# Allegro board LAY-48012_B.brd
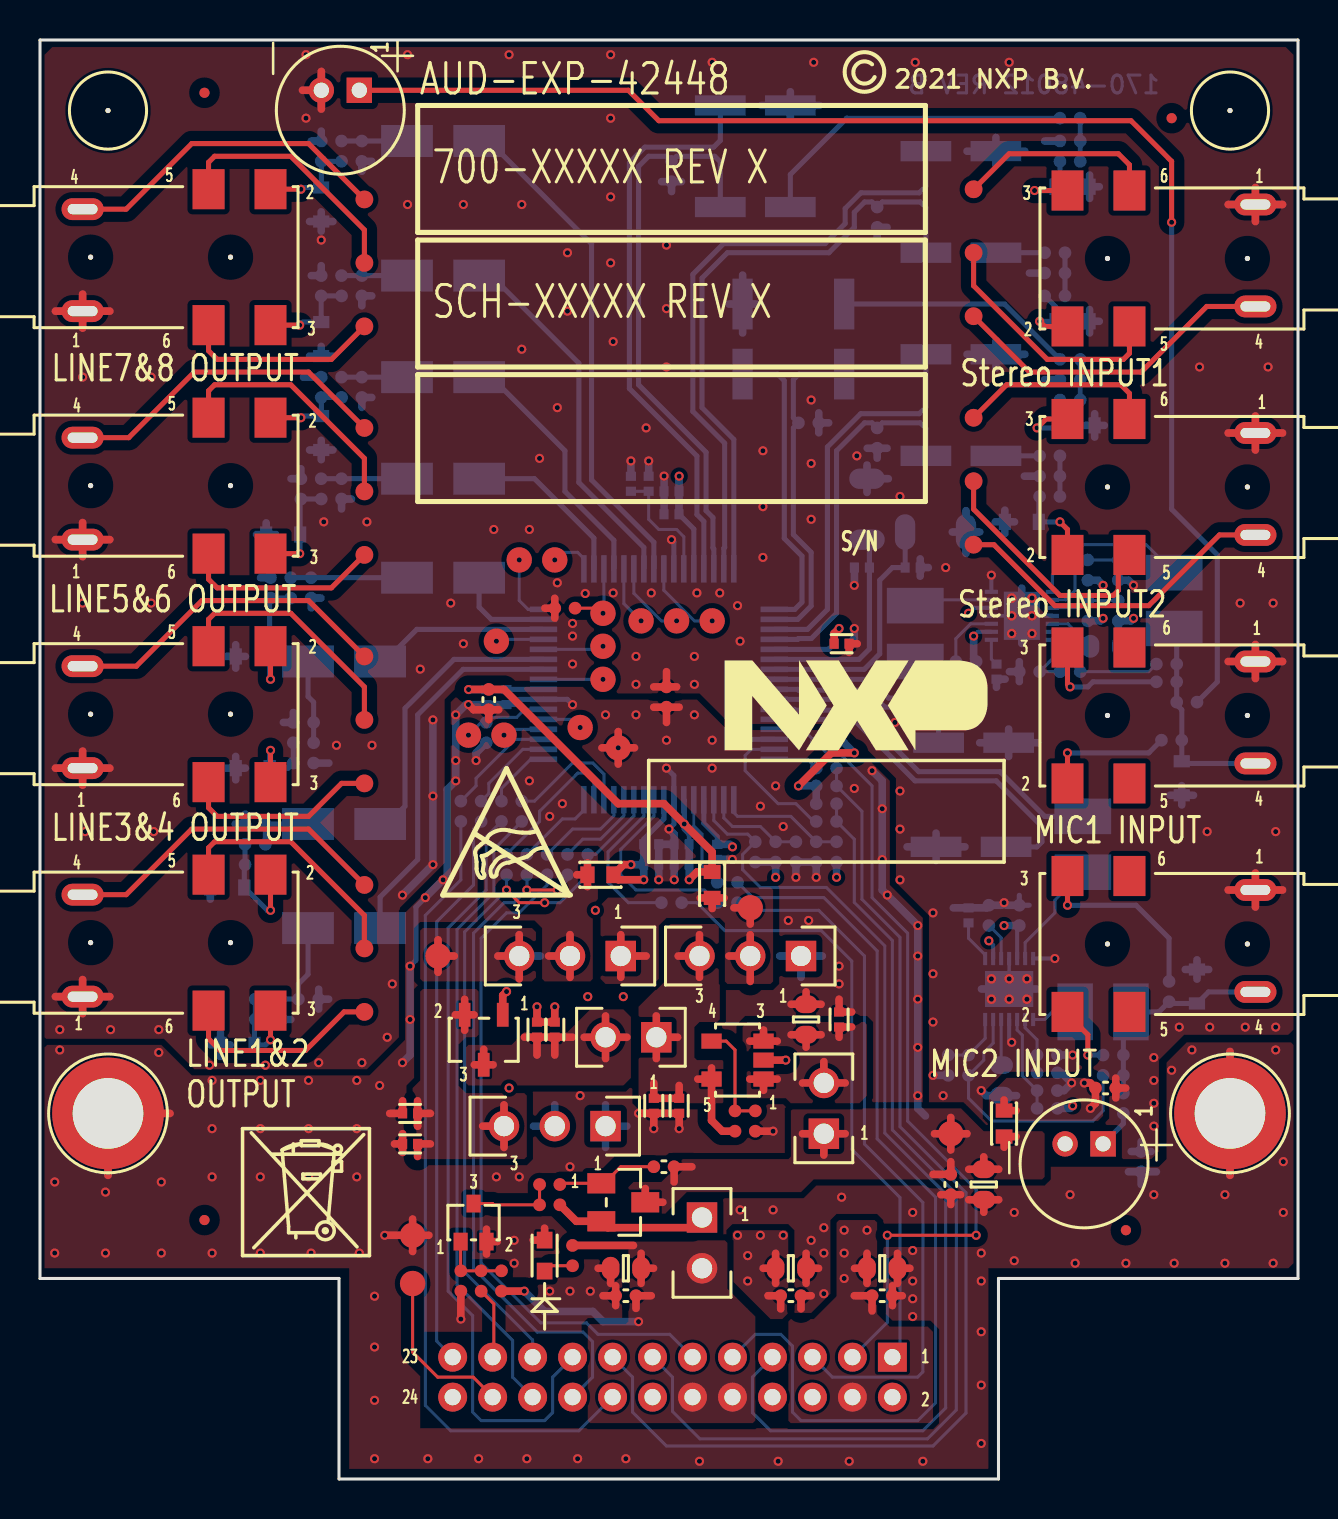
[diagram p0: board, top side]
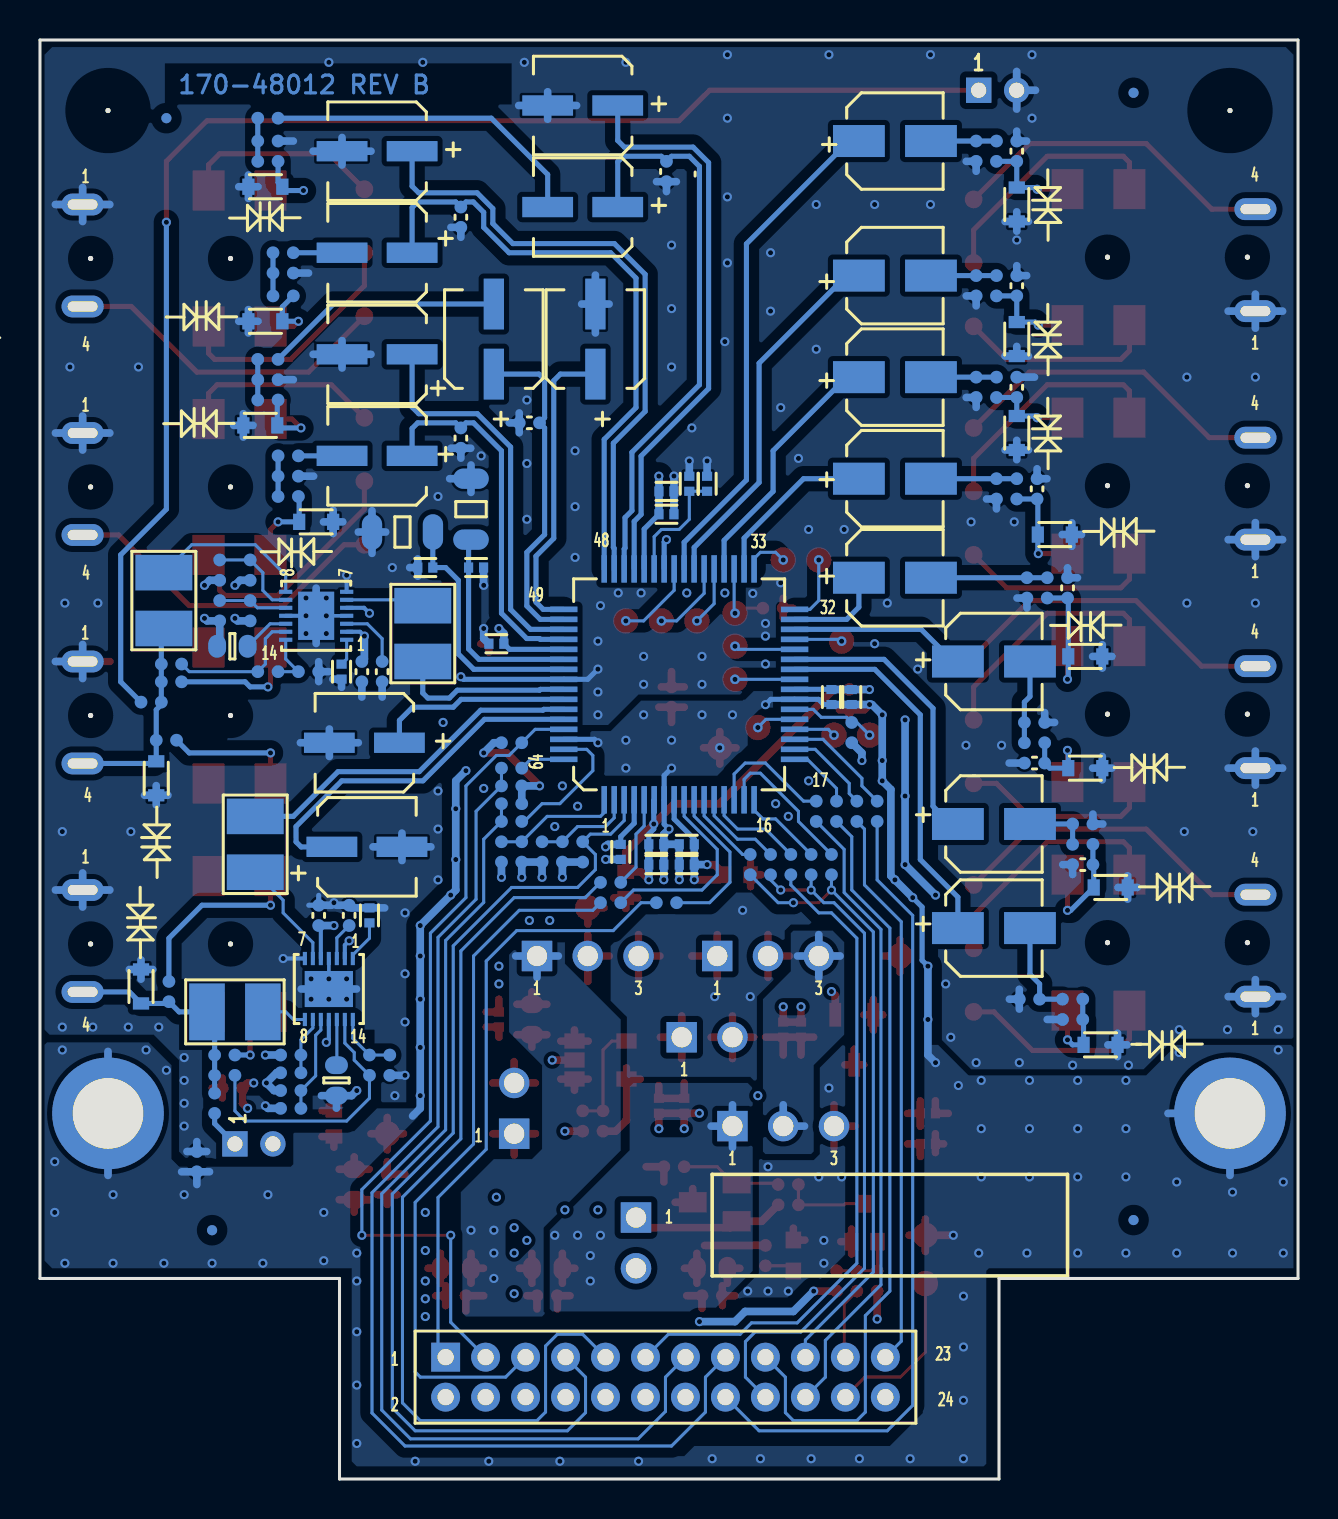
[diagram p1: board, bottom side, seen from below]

Outline 62.94 x 71.98 mm; copper layers: TOP, L2_GND1, L3_GND2, BOTTOM. Coordinates in mm from the lower left corner of the outline.
Outline path: 0,71.98 0,10.03 14.96,10.03 14.96,0 47.96,0 47.96,10.03 62.94,10.03 62.94,71.98 0,71.98

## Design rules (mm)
constraint set DEFAULT: min track width 0.152
net group CODEC_AUX_IN1: nets CODEC_AUX_IN1_N CODEC_AUX_IN1_P
net group CODEC_AUX_IN2: nets CODEC_AUX_IN2_N CODEC_AUX_IN2_P
net group CODEC_AUX_IN3: nets CODEC_AUX_IN3_N CODEC_AUX_IN3_P
net group CODEC_AUX_IN4: nets CODEC_AUX_IN4_N CODEC_AUX_IN4_P
net group CODEC_MIC1: nets CODEC_MIC1_N CODEC_MIC1_P
net group CODEC_MIC2: nets CODEC_MIC2_N CODEC_MIC2_P
net group 3W: nets ADC_LRCK ADC_SCLK AUX_LRCK AUX_SCLK DAC_LRCK DAC_SCLK DC_I2S1_MCLK DC_I2S1_RX_BCLK DC_I2S1_TX_BCLK SCL_CCLK
nets with their own width: min track width 0.254; nets AIN_1 AIN_2 AOUT_1 AOUT_2 AOUT_3 AOUT_4 AOUT_5 AOUT_6 AOUT_7 AOUT_8 CODEC_AOUT1_P CODEC_AOUT2_P CODEC_AOUT3_P CODEC_AOUT4_P CODEC_AOUT5_P CODEC_AOUT6_P CODEC_AOUT7_P CODEC_AOUT8_P MICIN_1 MICIN_2
nets with their own width: min track width 0.381; nets AGND GND

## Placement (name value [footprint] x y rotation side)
C1  10uF  [CC0603_OV]  42.14 10.54 0 top
C2  0.1UF  [CC0402_25]  42.14 9.17 0 top
C3  10uF  [CC0603_OV]  37.57 10.54 0 top
C4  0.1UF  [CC0402_25]  37.57 9.17 0 top
C5  10uF  [CC0603_OV]  29.31 10.54 180 top
C6  0.1UF  [CC0402_25]  29.31 9.17 180 top
C7  10uF  [CC0603_OV]  47.22 14.73 270 top
C8  0.1UF  [CC0402_25]  45.57 14.73 270 top
C9  10uF  [CC0603_OV]  38.33 22.99 90 top
C10  0.1UF  [0402_CC]  39.98 22.99 90 top
C11  4.7uF  [0402_CC]  30.71 18.67 270 top
C12  0.1UF  [0402_CC]  31.98 18.67 270 top
C13  2200PF  [CC0402_25]  31.22 15.62 0 top
C14  4.7uF  [0402_CC]  24.87 22.48 90 top
C15  0.1UF  [0402_CC]  25.76 22.48 90 top
C16  4.7uF  [0402_CC]  18.52 16.76 180 top
C17  0.1UF  [0402_CC]  18.52 18.29 180 top
C18  10uF  [CC0402_25]  53.31 19.56 0 top
C19  0.1UF  [0402_CC]  40.11 41.78 0 bottom
C20  0.1UF  [0402_CC]  31.6 48.26 180 bottom
C21  0.01uF  [0402_CC]  40.11 41.78 0 top
C22  0.01uF  [0402_CC]  31.6 49.4 180 bottom
C23  0.1UF  [0402_CC]  29.57 49.78 90 bottom
C24  4.7uF  [0402_CC]  30.45 49.78 90 bottom
C25  0.1UF  [0402_CC]  43.66 45.59 0 bottom
C26  100uF  [CC1206_OV]  44.81 47.37 0 bottom
C27  10uF  [CC0402_25]  22.45 38.99 270 top
C28  0.1UF  [0402_CC]  22.33 39.12 270 bottom
C29  0.1UF  [0402_CC]  32.11 31.75 180 bottom
C30  0.01uF  [0402_CC]  23.34 39.12 270 bottom
C31  0.01uF  [0402_CC]  32.11 30.73 180 bottom
C32  0.1UF  [0402_CC]  41.12 45.59 180 bottom
C33  100uF  [CC1206_OV]  41.38 48.51 90 bottom
C34  4.7uF  [0402_CC]  30.58 30.73 0 bottom
C35  0.1UF  [0402_CC]  33.88 31.37 270 bottom
C36  0.01uF  [0402_CC]  30.58 31.75 0 bottom
C37  1uF  [CC0402_25]  46.84 40.39 270 bottom
C38  1uF  [CC0402_25]  49 28.19 90 bottom
C39  0.47uF  [CC0603_OV]  53.31 41.66 180 bottom
C40  0.47uF  [CC0603_OV]  48.11 19.94 90 bottom
C41  0.1uF  [CC1210]  56.74 43.94 90 bottom
C42  0.1uF  [CC1210]  43.79 42.29 270 bottom
C43  0.1uF  [CC1210]  53.19 23.37 180 bottom
C44  0.1uF  [CC1210]  52.17 31.75 90 bottom
C45  4.7uF  [CCE40X54]  46.58 31.62 180 bottom
C46  0.1UF  [0402_CC]  47.85 40.39 270 bottom
C47  2.2UF  [CC0402_25]  45.82 40.39 270 bottom
C48  0.1UF  [0402_CC]  46.46 28.19 90 bottom
C49  2.2UF  [CC0402_25]  47.47 28.19 90 bottom
C50  4.7uF  [CCE40X54]  46.71 36.83 0 bottom
C51  10UF  [CCE40X54]  35.79 63.63 0 bottom
C52  2200pF  [CC0402_25]  31.6 65.41 270 bottom
C53  4.7uF  [CCE40X54]  35.79 68.71 0 bottom
C54  10UF  [CCE40X54]  46.08 61.34 0 bottom
C55  2200pF  [CC0402_25]  41.88 63.12 270 bottom
C56  4.7uF  [CCE40X54]  46.08 66.42 0 bottom
C57  3.3uF  [CC_A5]  15.21 27.56 180 bottom
C58  3.3uF  [CC_A5]  20.17 50.04 180 bottom
C59  2200pF  [CC0402_25]  11.28 22.99 0 bottom
C60  2200pF  [CC0402_25]  13.06 49.53 90 bottom
C61  3.3uF  [CC_A5]  15.21 32.77 180 bottom
C62  3.3uF  [CC_A5]  20.17 55.12 180 bottom
C63  2200pF  [CC0402_25]  10.77 30.73 0 bottom
C64  2200pF  [CC0402_25]  14.07 54.61 90 bottom
C65  3.3uF  [CC_A5]  15.21 40.89 180 bottom
C66  3.3uF  [CC_A5]  20.17 60.2 180 bottom
C67  2200pF  [CC0402_25]  13.18 35.81 0 bottom
C68  2200pF  [CC0402_25]  14.07 59.69 90 bottom
C69  3.3uF  [CC_A5]  20.17 45.09 180 bottom
C70  3.3uF  [CC_A5]  20.17 66.93 180 bottom
C71  2200pF  [CC0402_25]  11.53 44.58 90 bottom
C72  2200pF  [CC0402_25]  14.07 66.42 90 bottom
C73  10UF  [CCE40X54]  40.23 57.02 90 bottom
C74  10UF  [CCE40X54]  46.08 51.18 0 bottom
C75  2200pF  [CC0402_25]  38.46 52.83 0 bottom
C76  2200pF  [CC0402_25]  41.88 52.07 270 bottom
C77  4.7uF  [CCE40X54]  35.15 57.02 90 bottom
C78  4.7uF  [CCE40X54]  46.08 56.26 0 bottom
D1  RED  [LED_0603]  25.25 11.18 90 top
FB1  120OHM  [0603_CC]  48.23 17.78 90 top
FB2  120OHM  [0603_CC]  33.63 29.72 90 top
FB3  120OHM  [0603_CC]  28.04 30.23 0 top
H1  .635" LONG  [SPACER_139T]  3.4 18.29 0 top
H2  .635" LONG  [SPACER_139T]  59.54 18.29 0 top
J1  CON 2X12  [CON24_2MM_TH]  42.65 6.1 180 bottom
J2  HDR 1X2  [HDR102]  33.12 13.08 0 top
J3  HDR_1X3  [HDR103]  38.07 26.16 270 top
J4  HDR_1X3  [HDR103]  28.3 17.65 270 top
J5  HDR_1X3  [HDR103]  29.06 26.16 270 top
J6  PJ31360-I  [CON6_AUDJACK_RA_TH]  2.13 24.13 0 top
J7  PJ31360-I  [CON6_AUDJACK_RA_TH]  2.13 35.56 0 top
J8  PJ31360-I  [CON6_AUDJACK_RA_TH]  2.13 46.99 0 top
J9  PJ31360-I  [CON6_AUDJACK_RA_TH]  2.13 58.42 0 top
J10  PJ31360-I  [CON6_AUDJACK_RA_TH]  60.81 40.89 180 top
J11  PJ31360-I  [CON6_AUDJACK_RA_TH]  60.81 29.46 180 top
J12  PJ31360-I  [CON6_AUDJACK_RA_TH]  60.81 63.75 180 top
J13  HDR 1X2  [HDR102]  39.22 17.27 180 top
J14  HDR 1X2  [HDR102]  30.84 22.1 270 top
J15  PJ31360-I  [CON6_AUDJACK_RA_TH]  60.81 52.32 180 top
NOREF  -  []  41.25 70.36 0 top
NOREF#2  -  []  -6.27 24.03 0 top
NOREF#3  -  []  54.51 23.36 0 top
NOREF#4  -  []  20.65 4.1 90 top
NOREF#5  -  []  50.21 57.7 90 top
NOREF#6  -  []  60.41 49.62 90 top
NOREF#7  -  []  2.53 49.69 0 top
NOREF#8  -  []  -6.27 46.89 0 top
NOREF#9  -  []  -6.27 46.89 0 top
NOREF#10  -  []  -6.27 24.03 0 top
NOREF#11  -  []  -24.32 -55.33 0 top
NOREF#12  -  []  2.53 26.83 0 top
NOREF#13  -  []  2.13 35.56 90 top
NOREF#14  -  []  60.41 61.05 0 top
NOREF#15  -  []  -6.27 24.03 0 top
NOREF#16  -  []  30.45 30.86 0 top
NOREF#17  -  []  51.41 23.36 0 top
NOREF#18  -  []  -6.27 35.46 0 top
NOREF#19  -  []  -6.27 58.32 0 top
NOREF#20  -  []  22.2 20.72 90 top
NOREF#21  -  []  60.41 49.62 0 top
NOREF#22  -  []  -6.27 46.89 90 top
NOREF#23  -  []  11.53 34.86 90 top
NOREF#24  -  []  53.41 49.62 0 top
NOREF#25  -  []  51.41 34.79 0 top
NOREF#26  -  []  54.51 46.22 0 top
NOREF#27  -  []  -6.27 59.74 0 top
NOREF#28  -  []  60.81 58.65 0 top
NOREF#29  -  []  2.53 61.12 90 top
NOREF#30  -  []  20.17 29.21 0 top
NOREF#31  -  []  -6.27 35.46 90 top
NOREF#32  -  []  2.13 24.13 90 top
NOREF#33  -  []  14.96 0 0 top
NOREF#34  -  []  51.41 57.65 90 top
NOREF#35  -  []  54.51 57.65 0 top
NOREF#36  -  []  60.41 38.19 0 top
NOREF#37  -  []  -6.27 71.17 0 top
NOREF#38  -  []  83.13 188.21 0 top
NOREF#39  -  []  51.41 46.22 90 top
NOREF#40  -  []  53.41 61.05 0 top
NOREF#41  -  []  51.41 23.36 90 top
NOREF#42  -  []  60.81 47.22 0 top
NOREF#43  -  []  2.53 38.26 0 top
NOREF#44  -  []  60.41 26.76 0 top
NOREF#45  -  []  10.13 11.18 0 top
NOREF#46  -  []  50.21 57.7 0 top
NOREF#47  -  []  -6.27 35.46 0 top
NOREF#48  -  []  21.25 23.22 0 top
NOREF#49  -  []  -6.27 35.46 0 top
NOREF#50  -  []  40.65 6.1 0 top
NOREF#51  -  [unnamed#2]  8.23 12.95 0 top
NOREF#52  -  []  63.06 34.84 0 top
NOREF#53  -  []  54.51 34.79 0 top
NOREF#54  -  []  60.41 61.05 90 top
NOREF#55  -  []  2.13 58.42 90 top
NOREF#56  -  []  -6.27 46.89 0 top
NOREF#57  -  []  -6.27 24.03 90 top
NOREF#58  -  []  -307.51 308.83 0 top
NOREF#59  -  []  60.81 58.65 90 top
NOREF#60  -  []  63.06 46.27 0 top
NOREF#61  -  []  60.81 35.79 90 top
NOREF#62  -  []  -6.27 46.89 0 top
NOREF#63  -  []  11.53 57.72 90 top
NOREF#64  -  []  20.65 4.1 0 top
NOREF#65  -  []  -6.27 35.46 0 top
NOREF#66  -  []  60.81 47.22 90 top
NOREF#67  -  []  -6.27 58.32 0 top
NOREF#68  -  []  0 10.03 90 top
NOREF#69  -  []  18.9 62.36 0 top
NOREF#70  -  []  18.9 55.63 0 top
NOREF#71  -  []  60.81 35.79 0 top
NOREF#72  -  []  -351.94 -178.82 0 top
NOREF#73  -  []  -6.27 46.89 0 top
NOREF#74  -  []  2.53 38.26 90 top
NOREF#75  -  [unnamed#2]  59.54 68.45 0 top
NOREF#76  -  [unnamed#2]  54.33 12.45 0 top
NOREF#77  -  []  0 71.98 0 top
NOREF#78  -  []  50.21 23.41 0 top
NOREF#79  -  []  51.41 57.65 0 top
NOREF#80  -  []  51.41 46.22 0 top
NOREF#81  -  []  -6.27 58.32 0 top
NOREF#82  -  []  50.21 34.84 0 top
NOREF#83  -  []  47.96 0 90 top
NOREF#84  -  []  50.21 46.27 0 top
NOREF#85  -  []  0 10.03 0 top
NOREF#86  -  []  60.81 24.36 0 top
NOREF#87  -  []  2.13 46.99 90 top
NOREF#88  -  []  11.53 23.43 90 top
NOREF#89  -  []  51.41 34.79 90 top
NOREF#90  -  []  60.41 26.76 90 top
NOREF#91  -  [unnamed#2]  56.62 68.07 270 top
NOREF#92  -  []  50.21 46.27 90 top
NOREF#93  -  []  2.53 26.83 90 top
NOREF#94  -  []  -6.27 58.32 0 top
NOREF#95  -  []  60.81 24.36 90 top
NOREF#96  -  []  -6.27 36.88 0 top
NOREF#97  -  []  68.7 2.97 90 top
NOREF#98  -  []  60.41 38.19 90 top
NOREF#99  -  []  44 2.97 0 top
NOREF#100  -  []  50.21 23.41 90 top
NOREF#101  -  []  34.26 36.45 0 top
NOREF#102  -  []  53.41 26.76 0 top
NOREF#103  -  []  -162.62 126.36 0 top
NOREF#104  -  []  20.65 22.87 0 top
NOREF#105  -  []  -6.27 58.32 0 top
NOREF#106  -  []  47.96 0 0 top
NOREF#107  -  []  -6.27 35.46 0 top
NOREF#108  -  []  63.06 23.41 0 top
NOREF#109  -  []  50.21 34.84 90 top
NOREF#110  -  []  -6.27 24.03 0 top
NOREF#111  -  []  2.53 61.12 0 top
NOREF#112  -  []  -6.27 58.32 90 top
NOREF#113  -  []  11.53 46.29 90 top
NOREF#114  -  []  -6.27 48.31 0 top
NOREF#115  -  []  2.53 49.69 90 top
NOREF#116  -  []  -6.27 24.03 0 top
NOREF#117  -  [unnamed#2]  3.4 68.45 0 top
NOREF#118  -  []  18.9 48.89 0 top
NOREF#119  -  []  53.41 38.19 0 top
NOREF#120  -  []  63.06 57.7 0 top
NOREF#121  -  []  20.65 21.07 90 top
NOREF#122  -  [unnamed#2]  8.23 69.34 90 top
NOREF#123  -  []  14.96 0 90 top
NOREF#124  -  []  29.31 10.16 180 bottom
NOREF#125  -  [unnamed#2]  54.33 12.45 180 bottom
NOREF#126  -  [unnamed#2]  56.62 68.07 90 bottom
NOREF#127  -  [unnamed#2]  8.23 69.34 270 bottom
NOREF#128  -  [unnamed#2]  8.23 12.95 180 bottom
P1  EM6022P  [MIC_WM-63PR]  15.98 69.47 90 top
P2  EM6022P  [MIC_WM-63PR]  53.19 16.76 90 top
Q1  IRLML6401  [SOT-23]  29.18 13.84 270 top
Q2  2N7002BKW  [SC70_3]  21.69 12.83 0 top
R1  470  [RC0402_25]  26.64 11.18 270 top
R2  47K  [RC0402_25]  25.5 13.72 180 top
R3  464K  [RC0402_25]  34.77 17.91 90 top
R4  0  [RC0402_25]  22.07 9.91 90 top
R5  100K  [RC0402_25]  25.5 14.73 0 top
R6  200K  [RC0402_25]  35.79 17.91 270 top
R7  100K  [RC0402_25]  21.06 9.91 270 top
R9  0  [RC0402_25]  31.6 28.83 180 bottom
R10  0  [RC0402_25]  34.39 28.83 180 bottom
R11  0  [RC0402_25]  34.39 29.84 180 bottom
R12  0  [RC0402_25]  25.37 30.73 90 bottom
R14  0  [RC0402_25]  26.39 30.73 90 bottom
R15  0  [RC0402_25]  22.07 33.4 90 bottom
R16  0  [RC0402_25]  21.06 33.4 90 bottom
R17  0  [RC0402_25]  23.09 33.4 90 bottom
R18  0  [RC0402_25]  24.36 30.73 90 bottom
R19  0  [RC0402_25]  23.34 30.73 90 bottom
R20  0  [RC0402_25]  24.1 33.4 90 bottom
R21  0  [RC0402_25]  39.34 32.89 180 bottom
R22  0  [RC0402_25]  39.34 35.56 180 bottom
R23  10.0K  [RC0402_25]  22.33 37.34 270 bottom
R24  10.0K  [RC0402_25]  39.34 36.83 0 bottom
R25  2.0K  [RC0402_25]  39.34 33.78 180 bottom
R26  10.0K  [RC0402_25]  35.79 31.37 270 bottom
R27  2.0K  [RC0402_25]  39.34 34.67 180 bottom
R28  0  [RC0402_25]  55.09 15.88 90 bottom
R29  10.0K  [RC0402_25]  39.85 31.37 270 bottom
R30  10.0K  [RC0402_25]  36.8 31.37 270 bottom
R31  10.0K  [RC0402_25]  38.84 31.37 270 bottom
R32  10.0K  [RC0402_25]  37.82 31.37 270 bottom
R33  10.0K  [RC0402_25]  26.26 43.56 180 top
R34  0  [RC0402_25]  50.39 20.32 0 bottom
R35  0  [RC0402_25]  52.43 45.47 270 bottom
R36  0  [RC0402_25]  53.95 45.47 270 bottom
R37  0  [RC0402_25]  50.39 21.21 0 bottom
R38  2.2K  [RC0402_25]  56.36 40.77 180 bottom
R39  2.2K  [RC0402_25]  53.7 20.19 180 bottom
R40  150K  [RC0402_25]  46.46 20.7 270 bottom
R41  100K  [RC0402_25]  45.44 20.7 270 bottom
R42  150K  [RC0402_25]  51.54 40.39 0 bottom
R43  100K  [RC0402_25]  49.5 40.39 180 bottom
R44  0  [RC0402_25]  50.39 19.43 0 bottom
R45  0  [RC0402_25]  50.39 18.54 0 bottom
R46  0  [RC0402_25]  52.43 43.43 270 bottom
R47  0  [RC0402_25]  53.95 43.43 270 bottom
R48  2.49K  [RC0402_25]  51.54 65.91 0 bottom
R49  0  [RC0402_25]  51.54 68.07 180 bottom
R50  2.49K  [RC0402_25]  51.54 66.93 0 bottom
R51  2.49K  [RC0402_25]  50.77 59.18 0 bottom
R52  0  [RC0402_25]  50.77 61.34 180 bottom
R53  2.49K  [RC0402_25]  50.77 60.33 0 bottom
R54  470  [RC0402_25]  11.28 24 180 bottom
R55  470  [RC0402_25]  14.07 49.53 270 bottom
R56  10.0K  [RC0402_25]  13.44 24 0 bottom
R57  10.0K  [RC0402_25]  15.09 49.53 270 bottom
R58  470  [RC0402_25]  10.77 31.75 180 bottom
R59  470  [RC0402_25]  15.09 54.61 270 bottom
R60  10.0K  [RC0402_25]  10.77 32.77 180 bottom
R61  10.0K  [RC0402_25]  16.1 54.61 270 bottom
R62  470  [RC0402_25]  13.18 36.83 180 bottom
R63  470  [RC0402_25]  15.09 59.69 270 bottom
R64  10.0K  [RC0402_25]  13.18 37.85 180 bottom
R65  10.0K  [RC0402_25]  16.1 59.69 270 bottom
R66  470  [RC0402_25]  12.55 44.58 270 bottom
R67  470  [RC0402_25]  15.09 66.42 270 bottom
R68  10.0K  [RC0402_25]  13.56 44.58 270 bottom
R69  10.0K  [RC0402_25]  16.1 66.42 270 bottom
R71  0  [RC0402_25]  56.36 39.88 180 bottom
R72  0  [RC0402_25]  56.62 36.96 180 bottom
R73  0  [RC0402_25]  53.7 21.21 180 bottom
R74  0  [RC0402_25]  56.49 24.38 90 bottom
R75  2.49K  [RC0402_25]  51.54 53.97 0 bottom
R76  2.49K  [RC0402_25]  51.54 54.99 0 bottom
R77  0  [RC0402_25]  51.54 56.01 180 bottom
R78  2.49K  [RC0402_25]  50.52 49.15 0 bottom
R79  2.49K  [RC0402_25]  50.52 50.16 0 bottom
R80  0  [RC0402_25]  50.52 51.18 180 bottom
R81  0  [RC0402_25]  27.41 30.73 90 bottom
R82  0  [RC0402_25]  31.34 39.12 90 top
R83  1.0K  [RC0402_25]  23.09 9.91 90 top
R84  0  [RC0402_25]  57.38 38.86 180 bottom
R85  0  [RC0402_25]  54.2 18.8 90 bottom
TP1  -  [TPAD_050]  18.64 9.78 0 top
TP2  -  [TPAD_050]  18.64 12.19 0 top
TP3  -  [TPAD_050]  28.93 36.58 270 top
TP4  -  [TPAD_050]  45.57 17.27 0 top
TP5  -  [TPAD_050]  35.53 28.58 270 top
TP6  -  [TPAD_050]  19.91 26.16 270 top
TP7  -  [TPAD_050]  22.83 41.91 0 top
TP8  -  [TPAD_050]  23.98 45.97 0 top
TP9  -  [TPAD_050]  28.17 40 0 top
TP10  -  [TPAD_050]  28.17 41.66 0 top
TP11  -  [TPAD_050]  25.76 45.97 0 top
TP12  -  [TPAD_050]  30.07 42.93 0 top
TP13  -  [TPAD_050]  31.85 42.93 0 top
TP14  -  [TPAD_050]  27.03 37.59 0 top
TP15  -  [TPAD_050]  33.63 42.93 0 top
TP16  -  [TPAD_050]  23.22 37.21 0 top
TP17  -  [TPAD_050]  28.17 43.31 0 top
TP18  TP_35MIL  [TESTPOINT_35MIL]  16.23 26.54 90 top
TP19  TP_35MIL  [TESTPOINT_35MIL]  16.23 23.37 90 top
TP20  TP_35MIL  [TESTPOINT_35MIL]  16.23 29.72 90 top
TP21  TP_35MIL  [TESTPOINT_35MIL]  16.23 37.97 90 top
TP22  TP_35MIL  [TESTPOINT_35MIL]  16.23 34.8 90 top
TP23  TP_35MIL  [TESTPOINT_35MIL]  16.23 41.15 90 top
TP24  TP_35MIL  [TESTPOINT_35MIL]  16.23 49.4 90 top
TP25  TP_35MIL  [TESTPOINT_35MIL]  16.23 46.23 90 top
TP26  TP_35MIL  [TESTPOINT_35MIL]  16.23 52.58 90 top
TP27  TP_35MIL  [TESTPOINT_35MIL]  16.23 60.83 90 top
TP28  TP_35MIL  [TESTPOINT_35MIL]  16.23 57.66 90 top
TP29  TP_35MIL  [TESTPOINT_35MIL]  16.23 64.01 90 top
TP30  TP_35MIL  [TESTPOINT_35MIL]  46.71 61.34 270 top
TP31  TP_35MIL  [TESTPOINT_35MIL]  46.71 64.52 270 top
TP32  TP_35MIL  [TESTPOINT_35MIL]  46.71 58.17 270 top
TP33  TP_35MIL  [TESTPOINT_35MIL]  46.71 49.91 270 top
TP34  TP_35MIL  [TESTPOINT_35MIL]  46.71 53.09 270 top
TP35  TP_35MIL  [TESTPOINT_35MIL]  46.71 46.74 270 top
TP36  -  [TPAD_050]  21.44 37.21 0 top
TVS1  ESD5B5.0ST1G  [DIODE2_SOD523]  9.37 29.59 0 bottom
TVS4  ESD5B5.0ST1G  [DIODE2_SOD523]  9.88 21.72 0 bottom
TVS5  ESD5B5.0ST1G  [DIODE2_SOD523]  10.64 35.56 0 bottom
TVS6  ESD5B5.0ST1G  [DIODE2_SOD523]  10.64 41.15 0 bottom
TVS7  ESD5B5.0ST1G  [DIODE2_SOD523]  12.17 47.24 0 bottom
TVS8  ESD5B5.0ST1G  [DIODE2_SOD523]  14.07 52.32 90 bottom
TVS9  ESD5B5.0ST1G  [DIODE2_SOD523]  14.07 57.02 90 bottom
TVS10  ESD5B5.0ST1G  [DIODE2_SOD523]  14.07 63.75 90 bottom
TVS12  ESD5B5.0ST1G  [DIODE2_SOD523]  57.12 35.05 90 bottom
TVS13  ESD5B5.0ST1G  [DIODE2_SOD523]  57.89 24.64 270 bottom
TVS14  ESD5B5.0ST1G  [DIODE2_SOD523]  51.66 64.64 180 bottom
TVS15  ESD5B5.0ST1G  [DIODE2_SOD523]  51.66 57.91 180 bottom
TVS16  ESD5B5.0ST1G  [DIODE2_SOD523]  51.92 52.7 180 bottom
TVS17  ESD5B5.0ST1G  [DIODE2_SOD523]  49.12 47.88 0 bottom
U1  UM1750S-00  [SOT23-5_A]  34.9 20.95 180 top
U2  UM1550S-18  [SOT23-3-1P95]  22.2 21.97 180 top
U3  CS42448-DQZ  [LQFP64_0P5_10X10]  30.96 39.75 90 bottom
U4  MAX9814ETD+T  [TDFN14_0P4_3P1X3P1]  49.12 43.18 0 bottom
U5  MAX9814ETD+T  [TDFN14_0P4_3P1X3P1]  48.49 24.51 270 bottom

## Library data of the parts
C1-C20 C23-C29 C32-C35 C37-C44 C46-C49 C52 C55 C59 C60 C63 C64 C67 C68 C71 C72 C75 C76 = CAP_NP
C21 C22 C30 C31 C36 = CAP_NP: tolerance: 10%
C45 C50 C53 C56-C58 C61 C62 C65 C66 C69 C70 C77 C78 = CAP_POL: tolerance: 20%
C51 C54 C73 C74 = CAP_POL
D1 = LED
FB1-FB3 = BEAD_0: tolerance: 25%; room: RGMII_PHY
H1 H2 = SPACER
J1 = CONN_HDR_12X2
J2 J13 J14 = CONN_HDR_2X1
J3-J5 = CONN_HDR_3X1
J6-J12 J15 = CONN_AUDIOJACK_6P
P1 P2 = MIC_POM
Q1 = MOSFET_P
Q2 = NMOS_2N7002BKW_3P
R1-R3 R5-R7 R23-R27 R29-R33 R38-R43 R48 R50 R51 R53-R69 R75 R76 R78 R79 R83-R85 = RES
R4 R9-R12 R14-R22 R28 R34-R37 R44-R47 R49 R52 R71-R74 R77 R80-R82 = RES: tolerance: 5%
TP1-TP17 TP36 = TESTLOOP
TP18-TP35 = T POINT R: Tolerance: TOLERANCE; User Part Number: 510-75618
TVS1 TVS4-TVS10 TVS12-TVS17 = DIODE_TVS_BIDIR
U1 = UM1750S-00_5P
U2 = MCP1700
U3 = CS42448-DQ_LQFP64
U4 U5 = MAX9814_TDFN14

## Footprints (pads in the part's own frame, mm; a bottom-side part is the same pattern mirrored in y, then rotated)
0402_CC
  rect 0.457x0.508 smd: 1(-0.375,0) 2(0.375,0)
0603_CC
  rect 0.711x0.838 smd: 1(-0.65,0) 2(0.65,0)
CC0402_25
  round 0.635 smd: 1(-0.508,0) 2(0.508,0)
CC0603_OV
  oval 0.889x1.143 smd: 1(-0.762,0) 2(0.762,0)
CC1206_OV
  oval 1.016x1.778 smd: 1(-1.524,0) 2(1.524,0)
CC1210
  rect 1.778x2.845 smd: 1(-1.397,0) 2(1.397,0)
CC_A5
  rect 2.591x1.6 smd: 1(-1.803,0) 2(1.803,0)
CCE40X54
  rect 2.54x1.016 smd: 1(-1.753,0) 2(1.753,0)
CON6_AUDJACK_RA_TH
  round 0.254 hole 1.499 unplated: (0.4,2.7) (7.4,2.7)
  oval 2.108x1.092 hole 1.499x0.508: 1(0,0) 4(0,5.1)
  rect 1.6x2.007 smd: 2(9.4,6.1) 3(9.4,-0.7) 5(6.3,6.1) 6(6.3,-0.7)
CON24_2MM_TH
  rect 1.448x1.448 hole 0.813: 1(0,0)
  round 1.448 hole 0.813: 2(0,-2) 3(2,0) 4(2,-2) 5(4,0) 6(4,-2) 7(6,0) 8(6,-2) 9(8,0) 10(8,-2) 11(10,0) 12(10,-2) 13(12,0) 14(12,-2) 15(14,0) 16(14,-2) 17(16,0) 18(16,-2) 19(18,0) 20(18,-2) 21(20,0) 22(20,-2) 23(22,0) 24(22,-2)
DIODE2_SOD523
  rect 0.61x0.813 smd: 1(-0.85,0) 2(0.85,0)
HDR102
  rect 1.524x1.524 hole 1.016: 1(0,0)
  round 1.524 hole 1.016: 2(0,-2.54)
HDR103
  rect 1.524x1.524 hole 1.016: 1(0,0)
  round 1.524 hole 1.016: 2(0,-2.54) 3(0,-5.08)
LED_0603
  rect 0.838x0.787 smd: A(-0.775,0) C(0.775,0)
LQFP64_0P5_10X10
  rect 1.372x0.279 smd: 1(-5.775,3.75) 2(-5.775,3.25) 3(-5.775,2.75) 4(-5.775,2.25) 5(-5.775,1.75) 6(-5.775,1.25) 7(-5.775,0.75) 8(-5.775,0.25) 9(-5.775,-0.25) 10(-5.775,-0.75) 11(-5.775,-1.25) 12(-5.775,-1.75) 13(-5.775,-2.25) 14(-5.775,-2.75) 15(-5.775,-3.25) 16(-5.775,-3.75) 33(5.775,-3.75) 34(5.775,-3.25) 35(5.775,-2.75) 36(5.775,-2.25) 37(5.775,-1.75) 38(5.775,-1.25) 39(5.775,-0.75) 40(5.775,-0.25) 41(5.775,0.25) 42(5.775,0.75) 43(5.775,1.25) 44(5.775,1.75) 45(5.775,2.25) 46(5.775,2.75) 47(5.775,3.25) 48(5.775,3.75)
  rect 0.279x1.372 smd: 17(-3.75,-5.775) 18(-3.25,-5.775) 19(-2.75,-5.775) 20(-2.25,-5.775) 21(-1.75,-5.775) 22(-1.25,-5.775) 23(-0.75,-5.775) 24(-0.25,-5.775) 25(0.25,-5.775) 26(0.75,-5.775) 27(1.25,-5.775) 28(1.75,-5.775) 29(2.25,-5.775) 30(2.75,-5.775) 31(3.25,-5.775) 32(3.75,-5.775) 49(3.75,5.775) 50(3.25,5.775) 51(2.75,5.775) 52(2.25,5.775) 53(1.75,5.775) 54(1.25,5.775) 55(0.75,5.775) 56(0.25,5.775) 57(-0.25,5.775) 58(-0.75,5.775) 59(-1.25,5.775) 60(-1.75,5.775) 61(-2.25,5.775) 62(-2.75,5.775) 63(-3.25,5.775) 64(-3.75,5.775)
MIC_WM-63PR
  rect 1.27x1.27 hole 0.762: 1(0,0)
  round 1.27 hole 0.762: 2(0,1.9)
RC0402_25
  round 0.635 smd: 1(-0.508,0) 2(0.508,0)
SC70_3
  rect 0.711x0.889 smd: 1(-0.648,-0.952) 2(0.648,-0.952) 3(0,0.952)
SOT23-3-1P95
  rect 0.584x1.194 smd: 1(-0.953,-1.25) 2(0.953,-1.25) 3(0,1.25)
SOT23-5_A
  rect 1.016x0.762 smd: 1(-1.3,0.95) 2(-1.3,0) 3(-1.3,-0.95) 4(1.3,-0.95) 5(1.3,0.95)
SOT-23
  rect 1.016x1.397 smd: 1(-0.95,-1.1) 2(0.95,-1.1) 3(0,1.1)
SPACER_139T
  round 5.588 hole 3.531: 1(0,0)
TDFN14_0P4_3P1X3P1
  rect 0.66x0.203 smd: 1(-1.525,1.2) 2(-1.525,0.8) 3(-1.525,0.4) 4(-1.525,0) 5(-1.525,-0.4) 6(-1.525,-0.8) 7(-1.525,-1.2) 8(1.525,-1.2) 9(1.525,-0.8) 10(1.525,-0.4) 11(1.525,0) 12(1.525,0.4) 13(1.525,0.8) 14(1.525,1.2)
  rect 1.803x2.413 smd: 15(0,0)
TESTPOINT_35MIL
  round 0.889 smd: 1(0,0)
TPAD_050
  round 1.27 smd: 1(0,0)
unnamed#2
  round 0.508 smd: (0,0)

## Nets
AGND: C18.2 C19.2 C20.2 C21.2 C22.2 C23.2 C24.2 C25.2 C26.2 C32.2 C33.2 C37.2 C38.2 C39.1 C40.1 C45.2 C46.2 C47.2 C48.2 C49.2 C50.2 C52.2 C53.2 C55.2 C56.2 C59.2 C60.2 C63.2 C64.2 C67.2 C68.2 C71.2 C72.2 C75.2 C76.2 C77.2 C78.2 J6.1 J7.1 J8.1 J9.1 J10.1 J11.1 J12.1 J15.1 P1.2 P2.2 R28.2 R33.2 R36.2 R37.2 R41.2 R43.2 R45.2 R47.2 R50.1 R53.1 R56.2 R57.2 R60.2 R61.2 R64.2 R65.2 R68.2 R69.2 R76.1 R79.1 R82.2 TVS1.1 TVS4.1 TVS5.1 TVS6.1 TVS7.1 TVS8.1 TVS9.1 TVS10.1 TVS12.1 TVS13.1 TVS14.1 TVS15.1 TVS16.1 TVS17.1 U3.42 U3.56 U4.4 U4.7 U4.11 U4.15 U5.4 U5.7 U5.11 U5.15
GND: C1.2 C2.2 C3.2 C4.2 C5.2 C6.2 C7.2 C8.2 C9.2 C10.2 C11.2 C12.2 C14.2 C15.2 C16.2 C17.2 C27.2 C28.2 C29.2 C30.2 C31.2 C34.2 C35.2 C36.2 D1.C(CATHODE) H1.1(NC_1) H2.1(NC_1) J1.2 J1.6 J1.14 J1.24 Q2.2(SOURCE) R6.2 R7.2 R23.2 R28.1 R31.2 R32.2 R82.1 TP2.1(PIN1) TP3.1(PIN1) U1.2 U2.1 U3.7 U3.23 U3.62
P1V8: C3.1 C4.1 J1.8 J4.1
P1V8_S: C16.1 C17.1 J4.3 U2.2(VOUT)
P3V3: C1.1 C2.1 J1.4 J3.1
P3V3_S: C11.1 C12.1 J3.3 J14.1 R3.1 U1.5
P5V: C5.1 C6.1 J1.10 J1.12 J2.2 R1.1 R83.1
P5V_S: C7.1 C8.1 C13.2 FB1.1 J13.1 Q1.3 TP4.1(PIN1)
VCC_1V8: J4.2 J5.3 TP6.1(PIN1)
VCC_3V3: FB2.1 J3.2 J5.1 TP5.1(PIN1)
VCC_CODEC_3V3: C27.1 C28.1 C29.1 C30.1 C31.1 FB2.2 U3.6 U3.24
VCC_CODEC_5V0: C18.1 C19.1 C20.1 C21.1 C22.1 C37.1 C38.1 FB1.2 R34.2 R35.2 R44.2 R46.2 U3.44 U3.53 U4.2 U4.5(VDD) U5.2 U5.5(VDD)
VCC_CODEC_IO: C34.1 C35.1 C36.1 FB3.2 R24.2 R25.2 R26.2 R27.2 R29.2 R30.2 U3.4 U3.8
AD0_CS#: R29.1 R31.1 U3.1
AD1_CDIN: R30.1 R32.1 U3.2
ADC_LRCK: R11.2 U3.5
ADC_SCLK: R10.2 U3.9
ADC_SDOUT1: R12.2 U3.13
ADC_SDOUT2: R14.2 U3.12
ADC_SDOUT3: R81.2 U3.11
AIN_1: J12.3 R48.1 TVS14.2(A2)
AIN_2: J12.2 R51.1 TVS15.2(A2)
AIN_3: J15.3 R75.1 TVS16.2(A2)
AIN_4: J15.2 R78.1 TVS17.2(A2)
AMP1_A/R: R35.1 R36.1 U4.9
AMP1_BIAS: C39.2 U4.12
AMP1_CG: C47.1 U4.3
AMP1_CT: C46.1 U4.1
AMP1_GAIN_IN: R46.1 R47.1 U4.10
AMP1_MIC_IN: C41.2 U4.8
AMP1_MICBIAS: R38.2 R42.2 U4.13
AMP1_MICOUT: C42.1 U4.6
AMP1_TH_IN: R42.1 R43.1 U4.14
AMP2_A/R: R34.1 R37.1 U5.9
AMP2_BIAS: C40.2 U5.12
AMP2_CG: C49.1 U5.3
AMP2_CT: C48.1 U5.1
AMP2_GAIN_IN: R44.1 R45.1 U5.10
AMP2_MIC_IN: C43.2 U5.8
AMP2_MICBIAS: R39.2 R40.2 U5.13
AMP2_MICOUT: C44.1 U5.6
AMP2_TH_IN: R40.1 R41.1 U5.14
AOUT_1: C59.1 J6.3 R54.2 TVS4.2(A2)
AOUT_2: C63.1 J6.2 R58.2 TVS1.2(A2)
AOUT_3: C67.1 J7.3 R62.2 TVS5.2(A2)
AOUT_4: C71.1 J7.2 R66.2 TVS6.2(A2)
AOUT_5: C60.1 J8.3 R55.2 TVS7.2(A2)
AOUT_6: C64.1 J8.2 R59.2 TVS8.2(A2)
AOUT_7: C68.1 J9.3 R63.2 TVS9.2(A2)
AOUT_8: C72.1 J9.2 R67.2 TVS10.2(A2)
AUX_LRCK: TP16.1(PIN1) U3.20
AUX_SCLK: TP14.1(PIN1) U3.21
AUX_SDIN: R23.1 TP36.1(PIN1) U3.22
CODEC_AOUT1_P: C57.1 U3.26
CODEC_AOUT2_P: C61.1 U3.27
CODEC_AOUT3_P: C65.1 U3.30
CODEC_AOUT4_P: C69.1 U3.31
CODEC_AOUT5_P: C58.1 U3.34
CODEC_AOUT6_P: C62.1 U3.36
CODEC_AOUT7_P: C66.1 U3.39
CODEC_AOUT8_P: C70.1 U3.40
CODEC_AUX_IN1_N: C53.1 U3.45
CODEC_AUX_IN1_P: C51.1 C52.1 U3.46
CODEC_AUX_IN2_N: C56.1 U3.47
CODEC_AUX_IN2_P: C54.1 C55.1 U3.48
CODEC_AUX_IN3_N: C77.1 U3.49
CODEC_AUX_IN3_P: C73.1 C75.1 U3.50
CODEC_AUX_IN4_N: C78.1 U3.51
CODEC_AUX_IN4_P: C74.1 C76.1 U3.52
CODEC_MIC1_N: C50.1 U3.58
CODEC_MIC1_P: C42.2 U3.57
CODEC_MIC2_N: C45.1 U3.60
CODEC_MIC2_P: C44.2 U3.59
DAC_LRCK: R16.2 U3.19
DAC_SCLK: R15.2 U3.18
DAC_SDIN1: R17.2 U3.17
DAC_SDIN2: R18.2 U3.16
DAC_SDIN3: R19.2 U3.15
DAC_SDIN4: R20.2 U3.14
DC_GPIO1: J1.21 R4.1
DC_I2C_SCL: J1.13 R21.1 R25.1
DC_I2C_SDA: J1.15 R22.1 R27.1
DC_I2S1_MCLK: J1.1 R9.1
DC_I2S1_RX_BCLK: J1.5 R10.1
DC_I2S1_RX_D0: J1.11 R12.1
DC_I2S1_RX_SYNC: J1.9 R11.1
DC_I2S1_TX_BCLK: J1.23 R15.1
DC_I2S1_TX_D0: J1.17 R17.1
DC_I2S1_TX_D1: J1.18(B9) R14.1 R18.1
DC_I2S1_TX_D2: J1.19 R19.1 R81.1
DC_I2S1_TX_D3: J1.20 R20.1
DC_I2S1_TX_SYNC: J1.16 R16.1
DC_INT: J1.3 R24.1 U3.61
DC_RESET: J1.7 R26.1 U3.3
MCLK_IN: R9.2 U3.10
MICIN_1: C41.1 J10.4 R38.1 R71.1 R72.1 R84.2 TVS12.2(A2)
MICIN_2: C43.1 J11.4 R39.1 R73.1 R74.1 R85.2 TVS13.2(A2)
MUTEC_OUT: R33.1 TP17.1(PIN1) U3.35
SCL_CCLK: R21.2 U3.63
SDA_CDOUT: R22.2 U3.64
N16325068: FB3.1 J5.2
N16325522: TP9.1(PIN1) U3.25
N16325540: TP10.1(PIN1) U3.28
N16325558: TP7.1(PIN1) U3.29
N16325576: TP8.1(PIN1) U3.32
N16325594: TP11.1(PIN1) U3.33
N16325612: TP12.1(PIN1) U3.37
N16325620: TP13.1(PIN1) U3.38
N16325628: TP15.1(PIN1) U3.41
N16325638: C25.1 C26.1 U3.55
N16325678: C32.1 C33.1 U3.54
N16325718: C23.1 C24.1 U3.43(VQ)
N16334310: R48.2 R49.1 R50.2
N16334338: C51.2 R49.2
N16334434: R51.2 R52.1 R53.2
N16334446: C54.2 R52.2
N16339295: C61.2 R58.1 R60.1
N16339361: C65.2 R62.1 R64.1
N16339413: C58.2 R55.1 R57.1
N16339465: C62.2 R59.1 R61.1
N16339521: C66.2 R63.1 R65.1
N16339573: C57.2 R54.1 R56.1
N16343600: D1.A R1.2
N16357095: Q2.1 R4.2 R7.1 R83.2
N16357107: Q2.3 R2.2 R5.1
N16357127: J2.1 Q1.2(SOURCE) R2.1
N16357135: C13.1 Q1.1 R5.2
N16357758: R3.2 R6.1 U1.4
N16357876: C9.1 C10.1 J13.2 U1.1 U1.3(S\H\D\N\)
N16358335: C14.1 C15.1 J14.2 U2.3
N16404329: C69.2 R66.1 R68.1
N16404657: C70.2 R67.1 R69.1
N16406078: J1.22 TP1.1(PIN1)
N16452852: J10.2 R72.2
N16452871: J10.3 R71.2
N16456970: J6.5 TP18.1(TP)
N16456974: J6.6 TP19.1(TP)
N16456978: J6.4 TP20.1(TP)
N16457195: J7.5 TP21.1(TP)
N16457199: J7.6 TP22.1(TP)
N16457203: J7.4 TP23.1(TP)
N16457422: J8.5 TP24.1(TP)
N16457426: J8.6 TP25.1(TP)
N16457430: J8.4 TP26.1(TP)
N16457651: J9.5 TP27.1(TP)
N16457655: J9.6 TP28.1(TP)
N16457659: J9.4 TP29.1(TP)
N16458067: J12.4 TP32.1(TP)
N16458071: J12.6 TP31.1(TP)
N16458075: J12.5 TP30.1(TP)
N16458447: J11.3 R74.2
N16458491: J11.2 R73.2
N16475768: R75.2 R76.2 R77.1
N16475784: C73.2 R77.2
N16475838: R78.2 R79.2 R80.1
N16475850: C74.2 R80.2
N16477331: J15.4 TP35.1(TP)
N16477335: J15.6 TP34.1(TP)
N16477339: J15.5 TP33.1(TP)
N16544253: P1.1(OUT) R84.1
N16544784: P2.1(OUT) R85.1

Pads without a net: J10 5 6; J11 5 6

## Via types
v1: diameter 0.457, hole 0.254, TOP to BOTTOM, 313 vias
v2: diameter 0.483, hole 0.257, TOP to BOTTOM, 25 vias

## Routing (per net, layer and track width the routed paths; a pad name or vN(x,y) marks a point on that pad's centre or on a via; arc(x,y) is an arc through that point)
AGND: length 298.1
  TOP w0.381: 0.77,24.13 J6.1 ; J6.1 2.13,24.98 ; J6.1 2.13,23.28 ; J6.1 3.49,24.13 ; J9.1 2.13,59.27 ; J9.1 2.13,57.57 ; J9.1 0.77,58.42 ; J9.1 3.49,58.42 ; P1.2 14.08,70.41 ; P1.2 14.08,68.53 ; P1.2 13.14,69.47 ; 2.13,34.71 J7.1 ; J7.1 0.77,35.56 ; J7.1 3.49,35.56 ; J7.1 2.13,36.41 ; 59.45,29.46 J11.1 ; J11.1 60.81,28.61 ; J11.1 62.17,29.46 ; J11.1 60.81,30.32 ; 59.45,52.32 J15.1 ; J15.1 62.17,52.32 ; J15.1 60.81,53.18 ; J15.1 60.81,51.47 ; J12.1 60.81,64.61 ; J12.1 59.45,63.75 ; J12.1 62.17,63.75 ; J12.1 60.81,62.9 ; 0.77,46.99 J8.1 ; J8.1 3.49,46.99 ; J8.1 2.13,47.84 ; J8.1 2.13,46.14 ; 60.81,40.04 J10.1 ; J10.1 60.81,41.75 ; J10.1 62.17,40.89 ; J10.1 59.45,40.89 ; R33.2 25.76,44.06 ; R33.2 25.76,43.07 ; R33.2 25.26,43.56 ; R82.2 31.85,39.62 ; R82.2 30.71,39.62 ; R82.2 31.34,40.39 ; C18.2 54.32,19.56 ; C18.2 53.82,19.06 ; C18.2 53.82,20.05 ; 40.48,41.35 C21.2 40.89,41.78
  L2_GND1 w0.381: 59.45,52.32 J15.1 ; J15.1 60.81,51.47 ; J15.1 60.81,53.18 ; J15.1 62.17,52.32 ; J9.1 3.49,58.42 ; J9.1 2.13,57.57 ; J9.1 0.77,58.42 ; J9.1 2.13,59.27 ; J12.1 60.81,64.61 ; J12.1 59.45,63.75 ; J12.1 62.17,63.75 ; J12.1 60.81,62.9 ; J8.1 3.49,46.99 ; J8.1 2.13,46.14 ; J8.1 2.13,47.84 ; J8.1 0.77,46.99 ; 0.77,24.13 J6.1 ; J6.1 2.13,24.98 ; J6.1 2.13,23.28 ; J6.1 3.49,24.13 ; J7.1 3.49,35.56 ; J7.1 2.13,34.71 ; J7.1 0.77,35.56 ; J7.1 2.13,36.41 ; 50.35,16.76 P2.2 51.29,15.82 ; 13.14,69.47 P1.2 ; P1.2 14.08,70.41 ; P1.2 14.08,68.53 ; J11.1 60.81,30.32 ; J11.1 62.17,29.46 ; J11.1 59.45,29.46 ; J11.1 60.81,28.61 ; J10.1 62.17,40.89 ; J10.1 60.81,41.75 ; J10.1 59.45,40.89 ; J10.1 60.81,40.04
  L3_GND2 w0.381: 59.45,63.75 J12.1 ; J12.1 60.81,62.9 ; J12.1 62.17,63.75 ; J12.1 60.81,64.61 ; 13.14,69.47 P1.2 ; P1.2 14.08,70.41 ; P1.2 14.08,68.53 ; J10.1 62.17,40.89 ; J10.1 60.81,40.04 ; J10.1 60.81,41.75 ; J10.1 59.45,40.89 ; 2.13,57.57 J9.1 ; J9.1 2.13,59.27 ; J9.1 0.77,58.42 ; J9.1 3.49,58.42 ; J15.1 60.81,53.18 ; J15.1 59.45,52.32 ; J15.1 62.17,52.32 ; J15.1 60.81,51.47 ; J8.1 3.49,46.99 ; J8.1 2.13,47.84 ; J8.1 0.77,46.99 ; J8.1 2.13,46.14 ; J6.1 2.13,24.98 ; J6.1 0.77,24.13 ; J6.1 2.13,23.28 ; J6.1 3.49,24.13 ; 59.45,29.46 J11.1 ; J11.1 62.17,29.46 ; J11.1 60.81,28.61 ; J11.1 60.81,30.32 ; J7.1 3.49,35.56 ; J7.1 0.77,35.56 ; J7.1 2.13,36.41 ; J7.1 2.13,34.71
  BOTTOM w0.178: v2(48.49,25.02) U5.4 ; v2(48.62,43.18) U4.4
  BOTTOM w0.203: v1(50.77,26.04) U5.7 ; v2(49.63,43.18) U4.11 ; U5.11 48.49,21.97 v1(48.62,21.84) ; v1(47.6,45.21) U4.7
  BOTTOM w0.254: v1(41.88,40.13) 41.75,40 U3.56 36.74,40 35.54,40 v1(35.03,40.51) ; 49,29.2 C38.2 49.49,28.7 ; U3.42 31.71,46.87 v1(31.6,46.99)
  BOTTOM w0.381: C78.2 49.28,56.26 ; C78.2 47.83,56.95 ; C78.2 46.38,56.26 ; C78.2 47.83,55.57 ; 0.77,35.56 J7.1 ; J7.1 2.13,34.71 ; J7.1 2.13,36.41 ; J7.1 3.49,35.56 ; TVS17.1 48.76,47.88 ; TVS17.1 47.79,47.88 ; TVS17.1 48.27,48.46 ; TVS17.1 48.27,47.29 ; C56.2 49.28,66.42 ; C56.2 46.38,66.42 ; C56.2 47.83,65.73 ; C56.2 47.83,67.11 ; TVS1.1 9.01,29.59 ; TVS1.1 8.04,29.59 ; TVS1.1 8.52,29.01 ; TVS1.1 8.52,30.18 ; TVS8.1 14.07,51.96 ; TVS8.1 14.66,51.47 ; TVS8.1 14.07,50.99 ; TVS8.1 13.49,51.47 ; J9.1 2.13,59.27 ; J9.1 3.49,58.42 ; J9.1 2.13,57.57 ; J9.1 0.77,58.42 ; 12.18,37.85 R64.2 12.67,38.34 ; C25.2 44.44,45.59 ; C25.2 44.04,45.16 ; C25.2 44.04,46.03 ; 41.88,51.07 C76.2 ; C76.2 41.39,51.56 ; C76.2 42.38,51.56 ; 31.1,64.9 C52.2 ; C52.2 32.09,64.9 ; C52.2 31.6,64.4 ; 45.64,47.37 C26.2 ; C26.2 47.02,47.37 ; C26.2 46.33,48.44 ; C26.2 46.33,46.3 ; R28.2 55.59,16.38 ; R28.2 54.6,16.38 ; R28.2 55.09,16.88 ; C40.1 48.86,19.18 ; C40.1 47.35,19.18 v1(47.09,19.43) ; C40.1 48.11,18.55 ; 60.81,51.47 J15.1 ; J15.1 59.45,52.32 ; J15.1 60.81,53.18 ; J15.1 62.17,52.32 ; v1(40.74,44.7) 40.75,44.71 C32.2 ; 60.81,40.04 J10.1 ; J10.1 60.81,41.75 ; J10.1 62.17,40.89 ; 36.09,68.71 C53.2 ; C53.2 38.99,68.71 ; C53.2 37.54,68.02 ; C53.2 37.54,69.39 ; TVS16.1 52.77,53.29 ; TVS16.1 52.28,52.7 ; TVS16.1 53.25,52.7 ; TVS16.1 52.77,52.12 ; 45.69,28.57 C48.2 47.34,28.57 C49.2 48.11,28.7 v1(48.23,28.83) 48.36,28.7 C38.2 ; 56.54,34.2 TVS12.1 ; TVS12.1 57.12,33.72 ; TVS12.1 57.12,34.69 ; TVS12.1 57.71,34.2 ; TVS4.1 9.03,22.3 ; TVS4.1 9.03,21.13 ; TVS4.1 8.55,21.72 ; TVS4.1 9.51,21.72 ; J8.1 2.13,47.84 ; J8.1 2.13,46.14 ; J8.1 3.49,46.99 ; J8.1 0.77,46.99 ; 14.07,62.42 TVS10.1 ; TVS10.1 13.49,62.9 ; TVS10.1 14.66,62.9 ; TVS10.1 14.07,63.39 ; R36.2 54.46,44.96 v1(54.71,44.7) ; C77.2 35.15,60.22 ; C77.2 34.47,58.78 ; C77.2 35.84,58.78 ; C77.2 35.15,57.33 ; v1(19.66,37.97) v1(19.66,34.16) v1(19.66,30.73) v1(18.14,29.21) ; 9.79,40.56 TVS6.1 ; TVS6.1 9.79,41.73 ; TVS6.1 10.28,41.15 ; TVS6.1 9.31,41.15 ; 59.45,63.75 J12.1 ; J12.1 60.81,62.9 ; J12.1 60.81,64.61 ; J12.1 62.17,63.75 ; 41.38,49.35 C33.2 ; C33.2 42.44,50.04 ; C33.2 41.38,50.72 ; 13.49,56.17 TVS9.1 ; TVS9.1 14.66,56.17 ; TVS9.1 14.07,56.66 ; 14.07,67.42 14.07,66.93 13.58,66.93 ; 11.04,45.09 C71.2 11.53,45.58 ; 13.94,23.51 R56.2 ; R56.2 14.44,24 ; R56.2 13.94,24.5 ; 49.87,24.51 U5.15 47.1,24.51 ; TVS14.1 52.51,65.23 ; TVS14.1 52.51,64.06 ; TVS14.1 53,64.64 ; TVS14.1 52.03,64.64 ; TVS15.1 53,57.91 ; TVS15.1 52.51,58.5 ; TVS15.1 52.51,57.33 ; TVS15.1 52.03,57.91 ; C21.2 40.74,42.04 v1(40.74,42.55) ; P1.2 14.08,70.41 ; P1.2 13.14,69.47 ; P1.2 14.08,68.53 ; 0.77,24.13 J6.1 ; J6.1 2.13,24.98 ; J6.1 3.49,24.13 ; J6.1 2.13,23.28 ; C64.2 13.18,55.12 ; 13.69,35.81 14.45,35.81 ; 47.85,39.6 C46.2 48.29,40.01 ; 9.77,32.77 R60.2 10.26,33.26 ; C45.2 46.28,31.62 ; C45.2 44.83,32.31 ; C45.2 43.38,31.62 ; C45.2 44.83,30.94 ; C39.1 53.95,41.78 R47.2 54.58,42.93 v1(54.71,43.05) ; C50.2 49.91,36.83 ; C50.2 48.46,37.52 ; C50.2 47.01,36.83 ; C50.2 48.46,36.14 ; 16.1,53.61 R61.2 16.6,54.1 ; 9.79,34.98 TVS5.1 ; TVS5.1 9.79,36.14 ; TVS5.1 10.28,35.56 ; TVS5.1 9.31,35.56 ; C23.2 v1(29.57,50.93) ; J11.1 60.81,30.32 ; J11.1 60.81,28.61 ; J11.1 62.17,29.46 ; J11.1 59.45,29.46 ; TVS13.1 58.47,25.49 ; TVS13.1 57.3,25.49 ; TVS13.1 57.89,25.97 ; TVS13.1 57.89,25 ; 13.58,60.2 C68.2 14.07,60.69 ; 11.32,46.66 TVS7.1 ; TVS7.1 10.83,47.24 ; TVS7.1 11.32,47.83 ; TVS7.1 11.8,47.24 ; R45.2 51.54,18.54 v1(51.66,18.67) ; C75.2 39.46,52.83 ; C75.2 38.96,53.33 ; C75.2 38.96,52.34 ; C59.2 12.55,22.99 ; R50.1 50.27,66.93 ; 11.77,30.73 C63.2 11.28,30.24 ; 16.6,59.18 R65.2 16.1,58.69 ; v1(51.66,21.21) R37.2 ; 13.56,43.57 13.56,44.07 14.06,44.07 ; 16.6,65.91 R69.2 16.1,65.42 ; C24.2 v1(30.45,50.93) ; C20.2 C22.2 v1(31.22,50.17) ; R41.2 v1(44.68,20.19) ; C47.2 45.82,39.12 ; 41.88,62.12 C55.2 42.38,62.61 ; 49,39.89 R43.2 ; R43.2 48.5,40.39 ; R43.2 49,40.88 ; 49.12,44.56 U4.15 49.12,41.8 ; R53.1 49.5,60.33 ; C37.2 46.84,39.12 ; 12.56,50.04 C60.2 13.06,50.53 ; R79.1 49.25,50.16 ; R76.1 50.27,54.99 ; 15.09,48.53 R57.2 15.58,49.02
  vias: v1(0.99,22.48) v1(2.13,55.12) v1(2.13,43.81) v1(2.26,32.38) v1(3.53,22.48) v1(5.56,55.12) v1(5.56,43.81) v1(5.69,32.38) v1(5.94,22.48) v1(8.48,20.7) v1(11.28,20.7) v1(13.31,71.25) v1(13.31,68.07) v1(13.94,20.83) v1(14.07,61.98) v1(14.2,47.88) v1(14.83,36.7) v1(16.1,20.83) v1(16.36,47.88) v1(16.61,36.7) v1(17.37,22.1) v1(17.63,24.77) v1(18.39,71.25) v1(18.39,63.75) v1(19.02,40.51) v1(20.55,43.81) v1(21.18,63.75) v1(21.18,41.78) v1(22.71,47.5) v1(23.47,71.25) v1(24.1,63.75) v1(24.1,56.52) v1(24.49,47.5) v1(24.99,51.05) v1(25.88,53.59) v1(25.88,44.83) v1(26.39,61.34) v1(26.39,58.42) v1(26.64,42.8) v1(26.64,42.16) v1(26.64,40.77) v1(27.28,44.3) v1(28.55,71.25) v1(28.55,68.07) v1(28.55,64.14) v1(28.55,60.83) v1(28.68,56.9) v1(28.68,44.32) v1(29.82,41.15) v1(29.82,39.75) v1(30.33,52.58) v1(30.58,44.32) v1(31.34,61.72) v1(31.34,58.55) v1(31.34,55.63) v1(32.74,41.15) v1(32.74,39.75) v1(32.87,44.32) v1(33.63,70.87) v1(34.01,44.32) v1(34.9,43.69) v1(35.03,41.91) v1(35.03,39.37) v1(35.03,38.23) v1(36.17,51.44) v1(36.17,48.64) v1(36.17,46.1) v1(38.58,53.97) v1(38.58,50.8) v1(38.58,48.01) v1(38.71,70.87) v1(40.87,51.18) v1(42.77,37.85) v1(43.03,49.15) v1(43.03,34.42) v1(43.03,32.51) v1(43.03,29.97) v1(43.79,70.87) v1(44.68,28.32) v1(44.68,25.27) v1(44.68,22.86) v1(45.19,19.18) v1(45.31,45.59) v1(48.49,70.87) v1(55.73,21.08) v1(55.73,19.94) v1(55.73,18.8) v1(55.73,17.65) v1(57,22.61) v1(58.01,55.63) v1(58.39,32.38) v1(58.52,22.61) v1(60.05,43.81) v1(60.3,22.61) v1(61.44,55.63) v1(61.7,43.81) v1(61.82,32.38) v1(61.82,22.61) v2(47.6,25.02) v2(47.6,24) v2(48.49,24) v2(48.62,44.07) v2(48.62,42.29) v2(49.38,25.02) v2(49.38,24) v2(49.63,44.07) v2(49.63,42.29)
GND: length 172.6
  TOP w0.381: C1.2 42.9,11.29 ; C1.2 43.52,10.54 ; C1.2 42.9,9.79 ; 47.22,13.35 C7.2 ; C7.2 46.47,13.97 ; C7.2 47.97,13.97 ; C6.2 28.8,9.67 ; C6.2 28.8,8.67 ; C6.2 28.17,9.17 ; C27.2 22.95,38.48 ; C27.2 21.7,38.48 v1(21.44,38.74) ; C27.2 22.45,37.99 ; 24.68,11.95 D1.C 25.25,12.55 ; U1.2 v1(37.31,20.95) ; v2(28.93,36.58) 29.74,36.58 ; v2(28.93,36.58) 28.93,37.39 ; v2(28.93,36.58) 28.93,35.76 ; v2(28.93,36.58) 28.12,36.58 ; 45.57,13.73 C8.2 ; C8.2 46.06,14.22 ; C8.2 45.07,14.22 ; C3.2 38.95,10.54 ; C3.2 38.33,9.79 ; C3.2 38.33,11.29 ; R82.1 31.34,37.85 ; R82.1 31.98,38.61 ; R82.1 30.71,38.61 ; v1(23.34,24.38) 23.15,24.19 U2.1 ; C2.2 42.65,9.67 ; C2.2 43.14,9.17 ; C2.2 42.65,8.67 ; Q2.2 22.34,12.5 ; Q2.2 22.87,11.88 ; Q2.2 22.34,11.25 ; 39.98,24 C10.2 40.61,23.36 ; TP2.1 19.46,12.19 ; TP2.1 v1(17.25,12.19) ; TP2.1 18.64,11.38 ; TP2.1 18.64,13.01 ; C16.2 18.14,17.27 ; C16.2 18.14,16.33 ; C16.2 17.73,16.76 ; R6.2 v1(36.68,17.4) ; C11.2 C12.2 v1(31.98,17.53) ; C11.2 v1(29.95,18.29) ; C11.2 v1(30.71,17.53) ; 37.58,23.75 C9.2 ; C9.2 39.08,23.75 ; C9.2 38.33,24.37 ; 59.54,21.39 H2.1 59.54,15.19 ; 6.5,18.29 H1.1 3.4,15.19 ; 38.58,9.17 C4.2 38.07,8.51 ; 28.55,9.79 C5.2 27.93,10.54 ; 18.14,18.92 C17.2 17.5,18.29 ; R7.2 v1(21.06,8) ; v1(25.76,23.62) C15.2 C14.2 v1(24.87,23.62)
  L2_GND1 w0.381: 42.65,3.07 J1.2 43.68,4.1 ; 3.4,15.19 H1.1 ; H1.1 3.4,21.39 ; H1.1 6.5,18.29 ; J1.14 30.65,2.73 ; 59.54,21.39 H2.1 59.54,15.19 ; 20.65,3.07 J1.24 19.62,4.1
  L3_GND2 w0.381: 19.62,4.1 J1.24 20.65,3.07 ; 59.54,21.39 H2.1 59.54,15.19 ; J1.6 38.65,2.6 ; J1.14 30.65,2.6 ; H1.1 3.4,21.39 ; H1.1 3.4,15.19 ; H1.1 6.5,18.29 ; 43.68,4.1 J1.2 42.65,3.07
  BOTTOM w0.254: v1(26.64,38.73) 26.38,39 U3.23 23.99,39 23.73,38.74 C30.2 ; v1(19.28,29.08) 18.81,28.61 18.81,25.95 v1(18.52,25.65) ; v1(31.34,35.56) 31.71,35.19 U3.7 31.71,32.75 v1(31.47,32.51) ; U3.62 35.2,37 v1(35.03,36.83)
  BOTTOM w0.381: C35.2 v1(34.64,30.99) ; C30.2 C28.2 v1(21.44,38.74) 21.32,38.74 v1(20.8,38.23) v1(20.8,35.94) v1(20.8,34.92) 20.37,34.49 20.37,30.18 v1(20.17,29.97) v1(19.28,29.08) ; C29.2 C31.2 v1(31.73,29.98) ; C29.2 C36.2 C34.2 v1(30.96,29.98) ; C29.2 31.73,32.25 v1(31.47,32.51) ; 3.4,15.19 H1.1 6.5,18.29 ; v1(21.82,35.94) 21.82,36.32 R23.2 ; R28.1 55.85,15.37 ; R28.1 55.09,14.73 ; R28.1 54.46,15.37 ; 59.54,21.39 H2.1 59.54,15.19 ; 44.3,18.16 43.92,18.54 v1(43.92,19.18) v1(43.92,21.59) v1(43.92,24) v1(43.92,26.16) v1(43.92,27.69) v1(42.39,29.21) 42.14,29.46 v1(42.14,30.99) v1(42.14,33.53) 42.14,34.92 v1(41.63,35.43) ; v1(18.52,25.65) v1(18.52,22.99) 18.52,21.21 v1(18.14,20.83) ; v1(38.84,30.1) R31.2 R32.2 v1(37.82,30.1)
  vias: v1(0.74,14.86) v1(0.74,11.3) v1(0.99,21.46) v1(3.28,14.35) v1(3.28,11.3) v1(5.94,21.34) v1(6.07,14.86) v1(6.07,11.3) v1(8.61,19.94) v1(8.61,17.53) v1(8.61,15.11) v1(8.61,11.3) v1(11.02,19.94) v1(11.02,17.53) v1(11.02,15.11) v1(11.02,11.3) v1(13.44,19.94) v1(13.44,17.53) v1(13.44,15.11) v1(13.56,11.3) v1(15.85,19.94) v1(15.85,17.53) v1(15.85,15.11) v1(15.98,11.3) v1(16.74,9.14) v1(16.74,6.6) v1(16.74,3.94) v1(16.74,1.02) v1(16.99,19.68) v1(19.41,1.02) v1(21.95,1.02) v1(22.83,15.11) v1(23.47,19.56) v1(23.72,11.94) v1(23.72,10.79) v1(23.98,15.11) v1(24.36,1.02) v1(24.49,34.92) v1(25.5,33.15) v1(25.5,9.4) v1(26.14,33.78) v1(26.52,15.62) v1(26.52,9.4) v1(26.9,1.02) v1(27.03,19.18) v1(27.41,24.13) v1(27.53,9.4) v1(27.79,28.45) v1(28.3,38.23) v1(29.18,24.13) v1(29.31,1.02) v1(29.82,38.23) v1(31.34,36.96) v1(32.74,38.23) v1(32.99,0.89) v1(33.63,36.96) v1(33.63,35.56) v1(35.03,13.46) v1(36.04,33.66) v1(36.68,13.46) v1(36.8,34.67) v1(36.93,0.89) v1(37.19,32.64) v1(37.44,27.94) v1(38.46,27.94) v1(38.58,11.94) v1(39.22,12.57) v1(39.22,11.3) v1(39.22,9.27) v1(39.98,25.65) v1(39.98,24.77) v1(40.11,14.1) v1(40.49,0.89) v1(40.74,34.54) v1(43.66,13.34) v1(43.66,11.43) v1(43.66,9.91) v1(43.66,9.02) v1(43.66,8.13) v1(44.17,0.89) v1(47.09,11.3) v1(47.09,9.91) v1(47.09,7.37) v1(47.09,4.7) v1(47.09,1.78) v1(48.74,13.34) v1(48.74,10.92) v1(51.54,14.22) v1(51.79,10.79) v1(54.33,10.79) v1(55.73,14.22) v1(56.62,20.45) v1(56.74,10.79) v1(57.63,21.46) v1(59.28,14.22) v1(59.28,10.79) v1(61.7,10.79) v1(61.82,21.46) v1(62.2,15.88) v1(62.2,13.34)
P1V8: length 6.6
  TOP w0.381: C3.1 36.8,11.29 ; C3.1 36.8,9.79 ; C3.1 36.18,10.54 ; 36.42,9.17 37.06,9.17 37.06,8.51
  BOTTOM w0.381: J4.1 29.36,17.65 ; J4.1 28.3,18.72 ; J4.1 28.3,16.59
  vias: v1(34.9,12.19) v1(35.41,11.18) v1(35.41,9.91) v1(36.04,12.19) v1(37.19,12.19)
P1V8_S: length 8.9
  TOP w0.381: 19.53,16.76 C16.1 18.89,16.14 ; U2.2 21.25,24 ; U2.2 20.78,23.22 ; U2.2 21.25,22.45 ; U2.2 21.72,23.22 ; 23.22,16.59 J4.3 ; J4.3 23.22,18.72 ; J4.3 22.15,17.65 ; 18.9,17.65 18.89,17.66 C17.1 ; C17.1 18.89,18.92 ; C17.1 19.53,18.29
P3V3: length 7
  TOP w0.381: 41.63,8.41 C2.1 40.74,9.17 ; C1.1 41.38,11.29 ; C1.1 40.75,10.54 ; C1.1 41.38,9.79
  BOTTOM w0.381: J3.1 39.14,26.16 ; J3.1 38.07,25.09 ; J3.1 37.01,26.16
  vias: v1(40.23,12.45) v1(40.23,11.3) v1(40.23,10.03) v1(41.38,12.45)
P3V3_S: length 13.8
  TOP w0.381: 31.98,19.68 C12.1 C11.1 30.71,19.81 ; J14.1 31.9,22.1 ; J14.1 30.84,21.03 ; J14.1 30.84,23.17 ; J3.3 32.99,27.23 ; J3.3 32.99,25.09 ; J3.3 31.93,26.16 ; 32.91,20.01 U1.5 ; U1.5 33.6,20.56 ; U1.5 33.6,17.94 34.14,17.4 R3.1
P5V: length 14.1
  TOP w0.381: 30.07,9.79 C5.1 ; C5.1 30.07,11.29 ; C5.1 30.7,10.54 ; 29.69,11.68 R1.1 ; R83.1 v1(24.23,9.4) ; 30.58,9.17 C6.1 29.82,8.53
  BOTTOM w0.381: v1(24.23,9.4) 25.25,8.38 27.66,8.38 28.17,7.87 v1(29.95,7.87)
P5V_S: length 14.4
  TOP w0.381: 38.15,17.27 J13.1 ; J13.1 40.28,17.27 ; J13.1 39.22,16.2 ; 44.75,17.27 TP4.1 ; TP4.1 46.38,17.27 ; TP4.1 45.57,18.09 ; TP4.1 45.57,16.46 ; 30.28,14.53 Q1.3 31.16,13.84 ; 32.61,15.62 C13.2 31.72,14.86 ; 44.68,15.24 C8.1 45.57,15.88 ; 48.23,16.6 FB1.1 48.83,17.13 ; C7.1 47.22,16.12 ; C7.1 46.47,15.49 ; C7.1 47.97,15.49
VCC_1V8: length 12.1
  TOP w0.381: 22.91,26.16 J5.3 ; J5.3 23.98,27.23 ; J5.3 23.98,25.02 ; TP6.1 19.91,26.98 ; TP6.1 19.91,25.35 ; TP6.1 20.73,26.16
  BOTTOM w0.381: J5.3 25.04,26.16 ; J5.3 23.98,25.09 ; J5.3 22.91,26.16 ; J5.3 23.98,27.23 ; 24.69,17.65 J4.2 25.76,18.72
VCC_3V3: length 10.2
  TOP w0.381: J3.2 35.53,24.89 ; J3.2 35.53,27.23 ; J3.2 34.47,26.16 ; 33.63,28.53 FB2.1 ; FB2.1 34.23,29.07 ; FB2.1 33.03,29.07 ; 34.72,28.58 TP5.1 35.53,27.76 ; J5.1 29.06,27.23 ; J5.1 29.06,25.09 ; J5.1 30.33,26.16
VCC_CODEC_3V3: length 25.7
  TOP w0.381: v1(21.44,39.49) 21.45,39.5 C27.1 23.22,39.5 28.93,33.78 31.22,33.78 v1(32.23,32.77) 33.63,31.37 FB2.2 32.87,30.37 v1(32.48,29.98)
  BOTTOM w0.254: C29.1 32.48,32.26 32.23,32.51 v1(32.23,32.77) 32.23,33.96 U3.6 ; C30.1 23.35,39.5 U3.24
  BOTTOM w0.381: C29.1 C31.1 v1(32.48,29.98) ; v1(21.44,39.49) C28.1 C30.1
VCC_CODEC_5V0: length 23.2
  TOP w0.381: C21.1 39.73,42.3 v1(39.98,42.55) ; 48.83,18.43 FB1.2 48.23,18.96 ; v1(52.55,18.54) 52.81,18.8 C18.1 52.55,19.81 v1(52.25,19.81)
  BOTTOM w0.203: v1(47.47,26.92) 47.69,26.71 U5.2 ; U4.2 46.93,42.38 v1(46.71,42.16) ; C38.1 48.89,27.58 U5.5 ; U4.5 46.73,43.58 v1(46.46,43.31)
  BOTTOM w0.254: U3.53 39.45,41.5 C21.1 ; C20.1 32.71,47.52 U3.44
  BOTTOM w0.381: C37.1 46.71,41.02 v1(46.71,42.16) ; R44.2 51.23,19.43 v1(51.61,19.81) 51.1,20.32 R34.2 ; C20.1 C22.1 31.97,50.16 v1(31.98,50.16) ; v1(53.19,43.05) 53.06,42.93 R46.2 ; v1(39.98,42.55) 39.73,42.3 C21.1 ; R35.2 52.93,44.96 v1(53.19,44.7) ; v1(48.23,27.69) C38.1
VCC_CODEC_IO: length 20
  TOP w0.381: v1(30.21,29.98) 28.94,29.98 FB3.2 29.2,30.73 v1(29.57,30.73) ; v1(40.74,36.32) 39.6,36.32 v1(37.95,34.67)
  BOTTOM w0.254: C35.1 33.88,32.13 33.21,32.8 U3.4 ; U3.8 31.21,33.02 30.21,32.01 C36.1
  BOTTOM w0.381: v1(37.95,34.67) R27.2 R25.2 ; v1(36.8,30.1) R30.2 R26.2 ; C35.1 34.52,31.74 v1(34.65,31.62) ; C34.1 C36.1 ; C34.1 v1(30.21,29.98) ; C34.1 v1(29.57,30.73) ; R29.2 v1(39.85,30.1) ; 39.85,36.83 40.23,36.83 v1(40.74,36.32)
AD0_CS#: length 6.4
  BOTTOM w0.152: R29.1 R31.1 37.57,33.15 34.9,33.15 34.71,33.33 U3.1
AD1_CDIN: length 5
  BOTTOM w0.152: U3.2 34.21,33.07 34.65,32.64 36.04,32.64 R30.1 R32.1
ADC_LRCK: length 4.6
  BOTTOM w0.152: R11.2 33.12,30.61 33.12,32.26 32.71,32.67 U3.5
ADC_SCLK: length 9.8
  BOTTOM w0.152: R10.2 33.25,29.46 29.82,29.46 29.06,30.23 29.06,31.5 30.71,33.15 U3.9
ADC_SDOUT1: length 4.9
  BOTTOM w0.152: R12.2 26.64,32.51 28.04,32.51 28.71,33.18 U3.13
ADC_SDOUT2: length 4.4
  BOTTOM w0.152: R14.2 27.15,32 28.04,32 29.21,33.17 U3.12
ADC_SDOUT3: length 3.9
  BOTTOM w0.152: R81.2 27.79,31.24 29.71,33.17 U3.11
AIN_1: length 4.1
  TOP w0.254: J12.3 v1(49.76,64.45)
  BOTTOM w0.254: v1(49.76,64.45) 50.62,64.45 TVS14.2 51.03,64.86 R48.1
AIN_2: length 3.8
  TOP w0.254: J12.2 50.27,57.65 v1(50.01,57.91)
  BOTTOM w0.254: v1(50.01,57.91) TVS15.2 50.81,58.63 R51.1
AIN_3: length 4.2
  TOP w0.254: v1(49.89,52.58) 50.33,53.02 J15.3
  BOTTOM w0.254: R75.1 51.07,53.94 TVS16.2 50.94,52.58 v1(49.89,52.58)
AIN_4: length 4.2
  TOP w0.254: J15.2 51.41,47.5 v1(51.03,47.88)
  BOTTOM w0.254: R78.1 49.97,49.11 TVS17.2 v1(51.03,47.88)
AMP1_A/R: length 4.6
  BOTTOM w0.152: R36.1 R35.1 51.79,45.34 51.79,44.45 51.32,43.98 U4.9
AMP1_BIAS: length 2.4
  BOTTOM w0.152: C39.2 51.43,42.78 U4.12
AMP1_CG: length 3.2
  BOTTOM w0.152: U4.3 46.56,42.78 45.82,42.04 C47.1
AMP1_CT: length 1.3
  BOTTOM w0.152: U4.1 47.6,41.02 C46.1
AMP1_GAIN_IN: length 3.5
  BOTTOM w0.152: R47.1 R46.1 52.06,43.58 U4.10
AMP1_MIC_IN: length 8.1
  BOTTOM w0.152: C41.2 55.35,46.74 52.17,46.74 50.65,45.21 U4.8
AMP1_MICBIAS: length 6.9
  BOTTOM w0.152: R38.2 55.47,40.39 52.04,40.39 51.66,40.77 51.66,42.04 51.32,42.38 U4.13
AMP1_MICOUT: length 3.9
  BOTTOM w0.152: C42.1 44.08,43.98 U4.6
AMP1_TH_IN: length 2.9
  BOTTOM w0.152: U4.14 50.65,41.02 R43.1 R42.1
AMP2_A/R: length 2.9
  BOTTOM w0.152: R34.1 R37.1 49.89,21.97 49.29,22.57 U5.9
AMP2_BIAS: length 2.3
  BOTTOM w0.152: 48.11,20.7 48.09,20.72 U5.12
AMP2_CG: length 1.9
  BOTTOM w0.152: C49.1 48.09,27.07 U5.3
AMP2_CT: length 2.1
  BOTTOM w0.152: C48.1 46.46,27.05 47.29,26.22 U5.1
AMP2_GAIN_IN: length 4.9
  BOTTOM w0.152: U5.10 48.89,22.46 49.15,22.2 49.15,20.17 R44.1 R45.1
AMP2_MIC_IN: length 2.3
  BOTTOM w0.152: C43.2 50.65,23.37 50.27,22.99 U5.8
AMP2_MICBIAS: length 13.6
  BOTTOM w0.152: U5.13 47.69,21.81 47.22,21.34 47.22,20.95 R40.2 46.46,19.05 47.6,17.91 52.68,17.91 53.19,18.41 R39.2
AMP2_MICOUT: length 5.5
  BOTTOM w0.152: U5.6 49.29,26.84 50.77,28.32 50.77,28.96 C44.1
AMP2_TH_IN: length 3.1
  BOTTOM w0.152: U5.14 47.29,22.04 R40.1 R41.1
AOUT_1: length 4.7
  TOP w0.254: v1(11.53,21.97) J6.3
  BOTTOM w0.254: R54.2 C59.1 10.73,22.95 TVS4.2 11.28,21.72 v1(11.53,21.97)
AOUT_2: length 5.7
  TOP w0.254: J6.2 v1(11.53,28.45)
  BOTTOM w0.254: v1(11.53,28.45) 11.37,28.45 TVS1.2 10.22,30.69 C63.1 R58.2
AOUT_3: length 4.8
  TOP w0.254: v1(11.53,36.45) J7.3
  BOTTOM w0.254: v1(11.53,36.45) 11.49,36.41 TVS5.2 12.42,35.56 C67.1 R62.2
AOUT_4: length 6.8
  TOP w0.254: J7.2 v1(11.53,40)
  BOTTOM w0.254: 12.55,44.07 11.53,44.07 11.49,44.03 TVS6.2 11.49,40.05 v1(11.53,40)
AOUT_5: length 5.2
  TOP w0.254: v1(12.99,46.29) J8.3
  BOTTOM w0.254: R55.2 C60.1 13.02,48.98 TVS7.2 13.02,46.31 v1(12.99,46.29)
AOUT_6: length 4.5
  TOP w0.254: v1(13.05,53.09) 11.54,53.09 J8.2
  BOTTOM w0.254: v1(13.05,53.09) 13.14,53.17 TVS8.2 C64.1 R59.2
AOUT_7: length 4.9
  TOP w0.254: v1(12.99,57.72) J9.3
  BOTTOM w0.254: v1(12.99,57.72) 13.15,57.87 TVS9.2 C68.1 R63.2
AOUT_8: length 4.9
  TOP w0.254: J9.2 13.05,64.52 v1(13.05,64.52)
  BOTTOM w0.254: v1(13.05,64.52) 13.14,64.6 TVS10.2 C72.1 R67.2
AUX_LRCK: length 2.1
  BOTTOM w0.152: v2(23.22,37.21) 23.51,37.5 U3.20
AUX_SCLK: length 2
  BOTTOM w0.152: U3.21 26.62,38 v2(27.03,37.59)
AUX_SDIN: length 4.3
  BOTTOM w0.152: v2(21.44,37.21) 22.07,37.85 R23.1 22.58,38.1 23.85,38.1 24.25,38.5 U3.22
CODEC_AOUT1_P: length 18.7
  BOTTOM w0.254: U3.26 21.17,40.5 18.9,38.23 18.9,30.99 17.02,29.11 C57.1
CODEC_AOUT2_P: length 14.4
  BOTTOM w0.254: U3.27 20.71,41 18.26,38.55 18.26,33.66 17.37,32.77 C61.1
CODEC_AOUT3_P: length 8.8
  BOTTOM w0.254: U3.30 18.85,42.5 17.25,40.89 C65.1
CODEC_AOUT4_P: length 4.9
  BOTTOM w0.254: C69.1 21.97,43.61 22.58,43 U3.31
CODEC_AOUT5_P: length 8.5
  BOTTOM w0.254: U3.34 27.71,47.06 24.74,50.04 C58.1
CODEC_AOUT6_P: length 12.7
  BOTTOM w0.254: U3.36 28.71,46.95 26.26,49.4 26.26,51.44 22.58,55.12 C62.1
CODEC_AOUT7_P: length 18.4
  BOTTOM w0.254: C66.1 22.58,60.2 26.96,55.82 26.96,49.85 30.21,46.6 U3.39
CODEC_AOUT8_P: length 25.3
  BOTTOM w0.254: C70.1 22.45,66.93 27.6,61.79 27.6,49.97 30.71,46.86 U3.40
CODEC_AUX_IN1_N: length 28.6
  BOTTOM w0.254: U3.45 33.21,47.9 32.87,48.25 32.87,51.17 29.49,54.55 29.49,65.85 30.27,66.62 33.71,66.62 34.04,66.95 C53.1
CODEC_AUX_IN1_P: length 28.6
  BOTTOM w0.254: U3.46 33.71,46.53 33.67,46.57 33.67,48.09 33.32,48.44 33.32,51.36 29.95,54.74 29.95,65.66 30.45,66.17 31.34,66.17 C52.1 31.85,66.17 33.76,66.17 34.04,65.89 C51.1
CODEC_AUX_IN2_N: length 31.1
  BOTTOM w0.254: U3.47 34.21,46.56 34.26,46.6 34.26,51.81 32.66,53.4 32.66,60.26 34.2,61.8 39.28,61.8 40.28,62.8 40.28,63.55 41.07,64.34 43.99,64.34 44.32,64.67 C56.1
CODEC_AUX_IN2_P: length 31
  BOTTOM w0.254: C54.1 44.32,63.6 44.04,63.88 42.14,63.88 C55.1 41.63,63.88 41.26,63.88 40.74,63.36 40.74,62.61 39.47,61.34 34.39,61.34 33.12,60.07 33.12,53.59 34.71,52 U3.48
CODEC_AUX_IN3_N: length 15.2
  BOTTOM w0.254: C77.1 36.91,55.27 37.24,54.94 37.24,47.05 38.13,46.17 38.13,43.86 37.76,43.5 U3.49
CODEC_AUX_IN3_P: length 16.7
  BOTTOM w0.254: U3.50 37.91,43 38.58,43.67 38.58,46.36 37.69,47.24 37.69,52.58 C75.1 37.69,53.09 37.69,54.99 37.97,55.27 C73.1
CODEC_AUX_IN4_N: length 19.6
  BOTTOM w0.254: U3.51 38.4,42.5 39.4,43.5 39.4,51.62 41.06,53.29 43.99,53.29 44.32,53.62 C78.1
CODEC_AUX_IN4_P: length 18.5
  BOTTOM w0.254: U3.52 37.91,42 37.95,42.04 38.59,42.04 39.85,43.31 39.85,51.44 41.25,52.83 41.63,52.83 C76.1 42.14,52.83 44.04,52.83 44.32,52.55 C74.1
CODEC_MIC1_N: length 9.8
  BOTTOM w0.254: C50.1 44.96,37.95 44.3,38.61 42.27,38.61 41.87,39 U3.58
CODEC_MIC1_P: length 8.9
  BOTTOM w0.254: C42.2 43.79,39.32 43.54,39.07 42.46,39.07 42.06,39.46 37.95,39.46 37.9,39.5 U3.57
CODEC_MIC2_N: length 18.3
  BOTTOM w0.254: C45.1 49.87,31.62 50.13,31.87 50.13,32.64 47.84,34.92 43.78,34.92 40.7,38 U3.60
CODEC_MIC2_P: length 17.7
  BOTTOM w0.254: C44.2 50.27,33.15 48.03,35.38 43.97,35.38 40.89,38.46 37.78,38.46 37.74,38.5 U3.59
DAC_LRCK: length 5.6
  BOTTOM w0.152: R16.2 21.82,34.67 21.82,35.05 23.77,37 U3.19
DAC_SCLK: length 4.5
  BOTTOM w0.152: U3.18 24.16,36.5 22.45,34.8 22.45,34.29 R15.2
DAC_SDIN1: length 3.3
  BOTTOM w0.152: R17.2 23.09,34.54 24.55,36 U3.17
DAC_SDIN2: length 4.3
  BOTTOM w0.152: R18.2 26.14,33.02 26.77,33.02 27.21,33.46 U3.16
